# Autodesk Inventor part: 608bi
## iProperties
Shininess: 64.0
Length Units: 11269
Angle Units: 11279
Time Units: 11290
Mass Units: 11283
Length Display Precision: 3
Angle Display Precision: 2
Compacted: True
Part Number: 608bi
Document SubType Name: Modeling
Created: 2004-09
Material: Par défaut
Density: 1 g/cm^3
Density: 0.0
Volumn: 0.0
Area: 0.0
PropertySet Name: Model Information
Control State: 0
Master: False
Checked Out: False
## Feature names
1. Révolution1 [Revolution]
